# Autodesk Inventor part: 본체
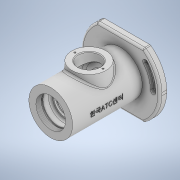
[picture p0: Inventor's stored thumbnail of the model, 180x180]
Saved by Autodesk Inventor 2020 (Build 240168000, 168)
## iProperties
Created: 2022-05
Part Number: 본체
Material: 일반
Document SubType Name: Modeling
Designer: Student
Density: 1 g/cm^3
Appearance: 기본값
Mass: 255.372 g
Surface Area: 626.719 cm^2
Volume: 255.372 cm^3
Author: Student
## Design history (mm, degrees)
sketch "스케치1"
  geometry: L1 (-33.985, -47)-(33.985, -47); L2 (57.967, -1.966)-(57.967, 1.966); L3 (33.985, 47)-(-33.985, 47); L4 (-57.967, 1.966)-(-57.967, -1.966); L5 (-57.967, -47)-(57.967, 47); L6 (57.967, -47)-(-57.967, 47); A1 r 58 centre (0, 0) between (-33.985, 47) and (-33.985, -47); A2 r 58 centre (0, 0) between (33.985, -47) and (33.985, 47); 1 further point
  constraints: 12 end point, 8 point on circle, 2 centre point, 2 midpoint, 2 parallel, 1 coincident, 1 horizontal, 1 perpendicular
  dimensions: "d0" = 94 distance between parallel lines of L1 L3; "d2" = 58 radius of A2; "d3" = 58 radius of A1; "d4" = 67.97058 distance of L1.start L1.end; "d47" = 50.9645 deg angle of L5 L2; "d48" = 50.9645 deg angle of L6 L2; "d49" = 115.93332 distance between parallel lines of L2 L4; "d50" = 57.96666 distance from line of point (0, 0) L2; "d51" = 0 distance from line of L5.end L2; "d52" = 0 distance from line of L6.start L2; "d53" = 115.93332 distance from line of L6.end L2; "d54" = 115.93332 distance from line of L5.start L2
extrude "돌출1" new body sketch "스케치1" distance "d5" = 10; taper "d6" = 0 deg
sketch "스케치2"
  geometry: C1 r 36 at (0, 0); 1 further point
  constraints: 1 centre point, 1 coincident
  dimensions: "d7" = 36 radius of C1
extrude "돌출2" join sketch "스케치2" distance "d8" = 3; taper "d9" = 0 deg
sketch "스케치3"
  geometry: C1 r 32 at (0, 0); 1 further point
  constraints: 1 centre point, 1 coincident
  dimensions: "d10" = 32 radius of C1
extrude "돌출3" join sketch "스케치3" distance "d11" = 102; taper "d12" = 0 deg
sketch "스케치4"
  geometry: L1 (0, -30.846)-(0, 129.662); L2 (32, 112)-(-32, 112) reference; L3 (22.5, 112)-(22.5, 104); L4 (22.5, 104)-(24, 104); L5 (24, 104)-(24, 101); L6 (24, 101)-(22.5, 101); L7 (22.5, 101)-(22.5, 90); L8 (22.5, 90)-(17.5, 90); L9 (17.5, 90)-(17.5, 87.75); L10 (17.5, 87.75)-(18.5, 87.75); L11 (18.5, 87.75)-(18.5, 86); L12 (18.5, 86)-(17.5, 86); L13 (17.5, 86)-(17.5, 75); L14 (17.5, 75)-(27, 75); L15 (27, 75)-(27, 37); L16 (27, 37)-(17.5, 37); L17 (17.5, 37)-(17.5, 26); L18 (17.5, 26)-(15, 26); L19 (15, 26)-(15, 21); L20 (15, 21)-(11, 21); L21 (11, 21)-(11, 18.3); L22 (11, 18.3)-(15, 18.3); L23 (-32, 10)-(32, 10) reference; L24 (-36, -3)-(36, -3) reference; L25 (20, 11)-(30, -3); L26 (15, 18.3)-(15, 11.7); L27 (15, 11.7)-(15.404, 11); L28 (15.404, 11)-(20, 11); L29 (30, -3)-(38.114, -17.054); 5 further points
  constraints: 52 end point, 16 perpendicular, 9 point on line, 3 vertical, 1 horizontal, 1 parallel
  dimensions: "d14" = 48 diameter of L5 L1; "d15" = 45 diameter of L7 L1; "d16" = 54 diameter of L15 L1; "d17" = 30 diameter of L19 L1; "d18" = 35 diameter of L9 L1; "d20" = 22 diameter of L21 L1; "d23" = 37 diameter of L11 L1; "d24" = 1.75 distance of L10.end L11.end; "d25" = 11 distance of L12.end L13.end; "d27" = 8 distance of L3.start L3.end; "d28" = 3 distance of L4.end L5.end; "d29" = 22 distance of L7.end L3.start; "d31" = 38 distance of L14.end L15.end; "d32" = 11 distance of L16.end L17.end; "d33" = 5 distance of L18.end L19.end; "d41" = 60 diameter of L25.end L1; "d42" = 40 diameter of L25.start L1; "d44" = 4 distance from line of L12.end L8; "d45" = 17.66206 distance from line of L1.end L2; "d46" = 142.84649 distance from line of L1.start L2; "d67" = 6.6 distance of L22.end L26.end; "d68" = 30 deg angle of L26 L27; "d69" = 30 diameter of L26 L1; "d70" = 0.7 vertical distance of L27.end L26.end; "d71" = 14 vertical distance of L25.end L25.start; "d109" = 129.05367 distance from line of L29.end L2; "d110" = 102 distance from line of point (20.714, 10) L2; "d111" = 0 distance from line of point (0, 112) L2; "d112" = 102 distance from line of point (0, 10) L2; "d113" = 1.54166 distance from line of point (20.714, 10) L29; "d114" = 31.51924 distance from line of point (0, 112) L29; "d115" = 19.48076 distance from line of point (0, 10) L29
revolve "회전1" sketch "스케치4" stored, may be unused: angle "d55" = 90 deg
node "작업 평면1"
sketch "스케치5"
  geometry: L1 (32, 112)-(-32, 112) reference; C1 r 25 at (0, 56); 1 further point
  constraints: 1 centre point
  dimensions: "d57" = 25 radius of C1; "d58" = 56 distance from line of L1 C1.centre; "d59" = 64.49806 distance of L1.start C1.centre
extrude "돌출4" join sketch "스케치5" stored distance "d60" = 10; taper "d61" = 5 deg
sketch "스케치6"
  geometry: L1 (33.985, 56)-(-33.985, 56) reference; C1 r 16 at (0, 0); 2 further points
  constraints: 1 centre point, 1 midpoint, 1 vertical alignment
  dimensions: "d62" = 16 radius of C1; "d63" = 56 distance of point (0, 56) C1.centre
extrude "돌출5" cut sketch "스케치6" distance "d64" = 20; taper "d65" = 0 deg
sketch "스케치7"
  geometry: L1 (-70.765, 0)-(82.559, 0); L2 (-36.77, -30.854)-(0, 0); L3 (0, 0)-(36.77, 30.854); A1 r 48 centre (0, 0) between (48, 0) and (-48, 0); A2 r 48 centre (0, 0) between (48, 0) and (36.77, 30.854); A3 r 52 centre (0, 0) between (52, 0) and (39.834, 33.425); A4 r 44 centre (0, 0) between (44, 0) and (33.706, 28.283); A5 r 4 centre (48, 0) between (44, 0) and (52, 0); A6 r 4 centre (36.77, 30.854) between (39.834, 33.425) and (33.706, 28.283); A7 r 58 centre (0, 0) between (57.967, 1.966) and (33.985, 47) reference; A8 r 48 centre (0, 0) between (-48, 0) and (-36.77, -30.854); A9 r 52 centre (0, 0) between (-52, 0) and (-39.834, -33.425); A10 r 44 centre (0, 0) between (-44, 0) and (-33.706, -28.283); A11 r 4 centre (-48, 0) between (-44, 0) and (-52, 0); A12 r 4 centre (-36.77, -30.854) between (-39.834, -33.425) and (-33.706, -28.283); A13 r 46.25 centre (0, 0) between (-46.25, 0) and (-35.43, -29.729); A14 r 1.75 centre (-48, 0) between (-46.25, 0) and (-49.75, 0); A15 r 49.75 centre (0, 0) between (-49.75, 0) and (-38.111, -31.979); A16 r 1.75 centre (-36.77, -30.854) between (-38.111, -31.979) and (-35.43, -29.729); A17 r 49.75 centre (0, 0) between (49.75, 0) and (38.111, 31.979); A18 r 1.75 centre (48, 0) between (46.25, 0) and (49.75, 0); A19 r 46.25 centre (0, 0) between (46.25, 0) and (35.43, 29.729); A20 r 1.75 centre (36.77, 30.854) between (38.111, 31.979) and (35.43, 29.729); 1 further point
  constraints: 38 point on circle, 19 centre point, 8 tangent, 6 end point, 3 coincident, 3 concentric, 1 horizontal, 6 other
  dimensions: "d66" = 48 radius of A1; "d72" = 4 radius of A6; "d73" = 4 radius of A12 (derived); "d74" = 40 deg angle of L1 L2; "d75" = 40 deg angle of L3 L1; "d76" = 1.96623 distance from line of A7.start L1; "d77" = 53.06809 distance from line of L1.end L3; "d78" = 33.42496 distance from line of A3.start L3; "d81" = 28.28265 distance from line of A10.start L3; "d82" = 45.48694 distance from line of L1.start L3; "d83" = 2.25 radial gap between concentric circles of A10 A13; "d84" = 2.25 radial gap between concentric circles of A3 A17
extrude "돌출6" cut sketch "스케치7" distance "d85" = 10; taper "d86" = 0 deg
extrude "돌출7" cut sketch "스케치7" distance "d87" = 4.4; taper "d88" = 0 deg
sketch "스케치8"
  geometry: A1 r 4 centre (-48, 0) between (-44, 0) and (-52, 0) reference; A2 r 4 centre (36.77, 30.854) between (39.834, 33.425) and (33.706, 28.283) reference; A3 r 4 centre (-36.77, -30.854) between (-39.834, -33.425) and (-33.706, -28.283) reference; 1 further point
sketch "스케치9"
  geometry: 1 further point
sketch "스케치10" dims "d96" = 20.5
  geometry: L1 (33.985, 56)-(-33.985, 56) reference; 4 further points
  constraints: 1 horizontal alignment, 1 midpoint, 1 vertical alignment, 2 other
  dimensions: "d97" = 56 distance of point (0, 56) point (0, 0); "d98" = 59.6343 distance of point (0, 56) point (-20.5, 0)
hole "구멍2" sketch "스케치10" at (-20.5, 0) diameter "d99" = 2.459; stored, may be unused: countersink angle "d103" = 90 deg, drill point angle "d105" = 118 deg; dims "d100" = 6, "d101" = 4, "d102" = 2, "d104" = 8
fillet "모깎기1" dims "d116" = 0.5
fillet "모깎기2" dims "d117" = 0.6
fillet "모깎기4" dims "d119" = 3
fillet "모깎기5" dims "d120" = 3
chamfer "모따기1" distance "d121" = 1; stored, may be unused: second distance "d122" = 2, angle "d123" = 45 deg
sketch "스케치11"
  geometry: C1 r 22.5 at (0, 0) reference; C2 r 22.5 at (0, 0); 1 further point
  constraints: 1 centre point, 1 coincident, 1 concentric
extrude "돌출8" join sketch "스케치11" distance "d124" = 8; taper "d125" = 0 deg
sketch "스케치12"
  geometry: C1 r 11 at (0, 0) reference; 1 further point
hole "구멍3" sketch "스케치12" at (0, 0) diameter "d126" = 43.376; stored, may be unused: countersink angle "d130" = 90 deg, drill point angle "d132" = 118 deg; dims "d127" = 8, "d128" = 4, "d129" = 2, "d131" = 10
node "작업 평면2"
sketch "스케치13"
  geometry: L1 (23.389, 86.887)-(23.389, 37.113); L2 (23.389, 37.113)-(-23.389, 37.113); L3 (-23.389, 37.113)-(-23.389, 86.887); L4 (-23.389, 86.887)-(23.389, 86.887); L5 (-36, -2)-(36, -2) reference; L6 (23.389, 62)-(-23.389, 62); L7 (46.4, 0)-(1.966, 0) reference; 3 further points
  constraints: 4 midpoint, 2 end point, 1 vertical alignment, 2 other
  dimensions: "d134" = 62 distance between parallel lines of L7 L6; "d135" = 86.88738 distance between parallel lines of L4 L7; "d136" = 46.77715 distance between parallel lines of L1 L3
feature "엠보싱1" sketch "스케치13" dims "d137" = 0.5, "d138" = 0
fillet "모깎기6" dims "d139" = 3
hole "구멍4" sketch "스케치8" diameter "d140" = 8; stored, may be unused: countersink angle "d144" = 90 deg, drill point angle "d146" = 0 deg; dims "d141" = 8, "d142" = 4, "d143" = 2, "d145" = 15
node "솔리드1"
pattern_circular "원형 패턴1" dims angle "d107" = 360 deg
feature "A9D066F2-1C7D-4E18-AEED-F7BC21143FA4" dims "d140" = 8, "d141" = 8, "d142" = 4, "d143" = 2, "d144" = 90 deg, "d145" = 15, "d146" = 0
other parameters: "d1" = 58, "d56" = 38, "d133" = 32
